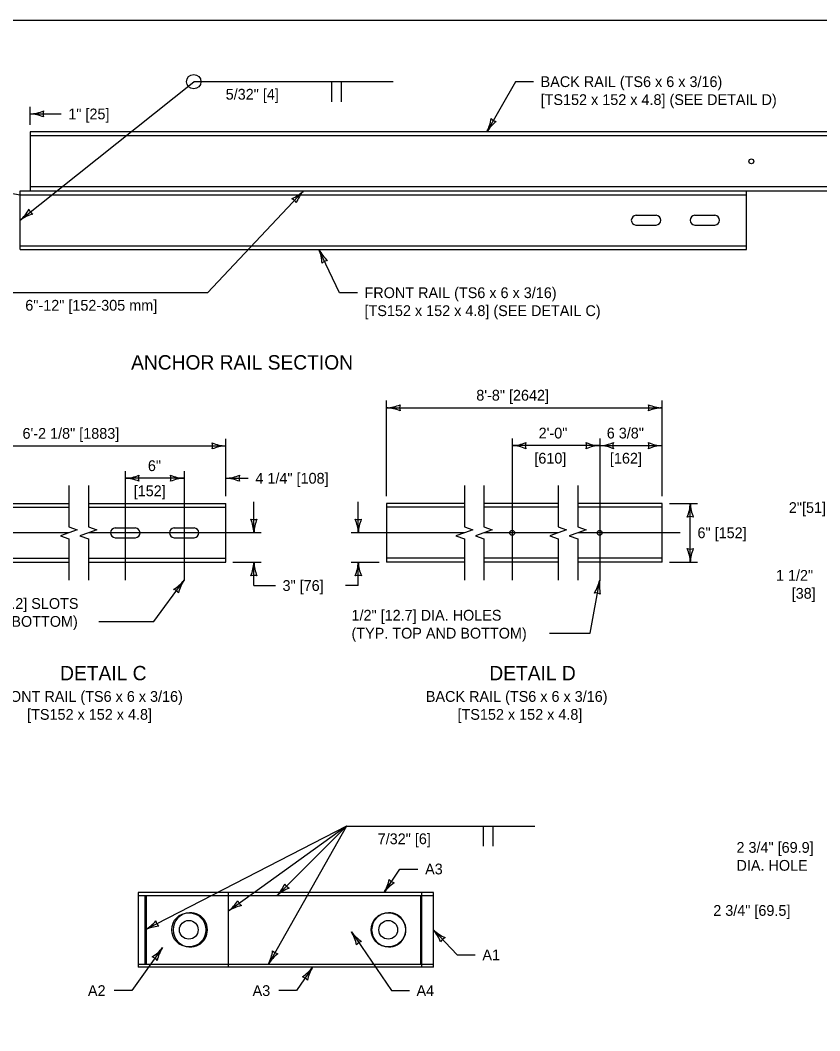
# Model space of a CAD drawing. Extents: x 49991.4 to 50021, y 49987.6 to 50011.4.
# Drawn here: x 50009.75 to 50014.2, y 49993.37 to 49999 of the extents above; entities that cross this region are included whole.
import ezdxf

# ---------------------------------------------------------------- set-up
doc = ezdxf.new("R2010")
doc.units = 0
for name, color, linetype in [('Level 1', 7, 'Continuous'), ('Level 2', 7, 'Continuous'), ('Level 3', 7, 'Continuous'), ('Level 4', 7, 'Continuous'), ('Level 5', 7, 'Continuous'), ('Level 6', 7, 'Continuous')]:
    doc.layers.add(name, color=color, linetype=linetype)

msp = doc.modelspace()

# ---------------------------------------------------------------- linework, layer by layer
at = {"layer": 'Level 1'}
for p, q in [((50015.4779, 49998.377), (50009.801, 49998.377)), ((50009.801, 49998.377), (50009.801, 49998.0488)), ((50009.7464, 49998.0488), (50015.4779, 49998.0488)), ((50009.7464, 49997.7213), (50009.7464, 49998.0488)), ((50013.7926, 49997.7213), (50013.7926, 49998.0488)), ((50013.1773, 49997.9123), (50013.289, 49997.9123)), ((50013.5048, 49997.9123), (50013.6165, 49997.9123)), ((50013.177, 49997.8578), (50013.2892, 49997.8578)), ((50013.5045, 49997.8578), (50013.6167, 49997.8578)), ((50009.7464, 49997.7213), (50013.7926, 49997.7213)), ((50009.3555, 49996.3075), (50010.0174, 49996.3075)), ((50010.126, 49996.3075), (50010.8916, 49996.3075)), ((50010.8916, 49995.98), (50010.8916, 49996.3075)), ((50011.7869, 49996.3075), (50011.7869, 49995.98)), ((50012.2209, 49996.3075), (50011.7869, 49996.3075)), ((50012.7438, 49996.3075), (50012.3295, 49996.3075)), ((50013.323, 49996.3075), (50012.8524, 49996.3075)), ((50013.323, 49995.98), (50013.323, 49996.3075)), ((50010.2762, 49996.1709), (50010.3879, 49996.1709)), ((50010.6037, 49996.1709), (50010.7154, 49996.1709)), ((50010.276, 49996.1163), (50010.3882, 49996.1163)), ((50010.6035, 49996.1163), (50010.7157, 49996.1163)), ((50009.3555, 49995.98), (50010.0174, 49995.98)), ((50010.126, 49995.98), (50010.8916, 49995.98)), ((50012.2209, 49995.98), (50011.7869, 49995.98)), ((50012.7438, 49995.98), (50012.3295, 49995.98)), ((50013.323, 49995.98), (50012.8524, 49995.98)), ((50012.0487, 49994.1404), (50010.4037, 49994.1404)), ((50010.4037, 49994.1404), (50010.4037, 49993.7237)), ((50010.4037, 49994.1231), (50012.0487, 49994.1231)), ((50010.4428, 49993.7411), (50010.4428, 49994.1231)), ((50010.9069, 49993.7237), (50010.9069, 49994.1404)), ((50011.9792, 49993.7411), (50011.9792, 49994.1231)), ((50011.9844, 49993.7237), (50011.9844, 49994.1404)), ((50012.0487, 49993.7237), (50012.0487, 49994.1404)), ((50010.4037, 49993.7411), (50012.0487, 49993.7411)), ((50012.0487, 49993.7237), (50010.4037, 49993.7237))]:
    msp.add_line(p, q, dxfattribs=at)
msp.add_lwpolyline([(49999.3835, 49998.9992), (50016.7501, 49998.9992), (50016.7501, 49987.7988), (49999.3835, 49987.7988)], close=True, dxfattribs=at)
for centre, radius in [((50013.8199, 49998.2132), 0.0136), ((50012.487, 49996.1437), 0.0136), ((50012.975, 49996.1437), 0.0136), ((50010.6858, 49993.9321), 0.0955), ((50011.7969, 49993.9321), 0.0955), ((50010.6858, 49993.9321), 0.0521), ((50011.7969, 49993.9321), 0.0521)]:
    msp.add_circle(centre, radius, dxfattribs=at)
for centre, radius, start, end in [((50013.1785, 49997.885), 0.0273, 92.5686, 266.9422), ((50013.2878, 49997.885), 0.0273, 273.0578, 87.4314), ((50013.506, 49997.885), 0.0273, 92.5686, 266.9422), ((50013.6153, 49997.885), 0.0273, 273.0578, 87.4314), ((50010.2774, 49996.1436), 0.0273, 92.5686, 266.9422), ((50010.3867, 49996.1436), 0.0273, 273.0578, 87.4314), ((50010.6049, 49996.1436), 0.0273, 92.5686, 266.9422), ((50010.7142, 49996.1436), 0.0273, 273.0578, 87.4314), ((50010.6941, 49993.9321), 0.0955, 92.4902, 267.5098), ((50011.8, 49993.9321), 0.0955, 90.9215, 269.0785)]:
    msp.add_arc(centre, radius, start, end, dxfattribs=at)
at = {"layer": 'Level 3'}
for p, q in [((50009.7464, 49997.8851), (50010.7131, 49998.6568)), ((50011.8238, 49998.6568), (50010.7131, 49998.6568)), ((50011.4804, 49998.6568), (50011.4804, 49998.5453)), ((50011.5339, 49998.6568), (50011.5339, 49998.5453)), ((50009.801, 49998.417), (50009.801, 49998.517)), ((50009.801, 49998.477), (50009.9745, 49998.477)), ((50011.7869, 49996.3475), (50011.7869, 49996.8801)), ((50013.323, 49996.3475), (50013.323, 49996.8801)), ((50011.7869, 49996.8401), (50013.323, 49996.8401)), ((50010.8916, 49996.3475), (50010.8916, 49996.6675)), ((50009.3555, 49996.6275), (50010.8916, 49996.6275)), ((50012.975, 49996.6292), (50012.487, 49996.6292)), ((50012.975, 49996.6292), (50013.323, 49996.6292)), ((50010.6596, 49996.4475), (50010.3321, 49996.4475)), ((50010.8916, 49996.4475), (50011.0168, 49996.4475)), ((50011.0484, 49996.1437), (50011.0484, 49996.3171)), ((50011.6301, 49996.1437), (50011.6301, 49996.3171)), ((50013.363, 49996.3075), (50013.5198, 49996.3075)), ((50013.4798, 49995.98), (50013.4798, 49996.3075)), ((50010.9316, 49995.98), (50011.0884, 49995.98)), ((50011.0484, 49995.8499), (50011.0484, 49995.98)), ((50011.5901, 49995.98), (50011.7469, 49995.98)), ((50011.6301, 49995.8499), (50011.6301, 49995.98)), ((50013.363, 49995.98), (50013.5198, 49995.98)), ((50010.491, 49995.65), (50010.6596, 49995.88)), ((50012.9225, 49995.5845), (50012.975, 49995.88)), ((50011.0484, 49995.8499), (50011.1679, 49995.8499)), ((50011.6301, 49995.8499), (50011.559, 49995.8499)), ((50010.1847, 49995.65), (50010.491, 49995.65)), ((50012.6959, 49995.5845), (50012.9225, 49995.5845)), ((50011.5644, 49994.5089), (50010.4428, 49993.9321)), ((50011.5644, 49994.5089), (50010.9069, 49994.0362)), ((50011.5644, 49994.5089), (50011.1298, 49993.7411)), ((50011.5644, 49994.5089), (50011.1786, 49994.1231)), ((50012.3258, 49994.5089), (50012.3258, 49994.3974)), ((50012.3793, 49994.5089), (50012.3793, 49994.3974)), ((50012.0487, 49993.9321), (50012.1814, 49993.7923)), ((50010.5395, 49993.8332), (50010.369, 49993.5934)), ((50012.1814, 49993.7923), (50012.2814, 49993.7923)), ((50010.369, 49993.5934), (50010.269, 49993.5934))]:
    msp.add_line(p, q, dxfattribs=at)
for points in [[(50012.6058, 49998.6568), (50012.5058, 49998.6568), (50012.3465, 49998.377)], [(50011.3246, 49998.0488), (50010.7894, 49997.4811), (50008.2254, 49997.4811)], [(50011.6247, 49997.4811), (50011.5247, 49997.4811), (50011.4108, 49997.7213)], [(50011.5644, 49994.5089), (50012.6133, 49994.5089)], [(50011.7736, 49994.1404), (50011.8623, 49994.2708), (50011.9623, 49994.2708)], [(50011.5916, 49993.9207), (50011.8144, 49993.5934), (50011.9144, 49993.5934)], [(50011.3753, 49993.7237), (50011.2866, 49993.5934), (50011.1866, 49993.5934)]]:
    msp.add_lwpolyline(points, dxfattribs=at)
msp.add_circle((50010.7131, 49998.6568), 0.0401, dxfattribs=at)
msp.add_circle((50010.7131, 49998.6568), 0.0401, dxfattribs=at)
for centre, radius, start, end in [((50009.7919, 49998.6991), 0.2223, 272.3605, 292.544), ((50009.7895, 49998.2443), 0.233, 67.9228, 87.1727), ((50009.9292, 49998.477), 0.0548, 162.1388, 197.8612), ((50012.1386, 49998.4822), 0.233, 333.1604, 352.4103), ((50012.4099, 49998.4884), 0.0548, 222.4719, 258.1943), ((50012.5349, 49998.2591), 0.2223, 127.7891, 147.9726), ((50011.1692, 49998.2078), 0.2223, 294.1475, 314.331), ((50011.2366, 49997.9555), 0.0548, 28.8303, 64.5526), ((50011.5018, 49997.8976), 0.233, 139.5188, 158.7686), ((50009.5923, 49998.0598), 0.233, 311.4286, 330.6784), ((50009.8466, 49997.9651), 0.0548, 200.7401, 236.4624), ((50009.8779, 49997.7057), 0.2223, 106.0573, 126.2408), ((50011.2062, 49997.6344), 0.2223, 2.818, 23.0015), ((50011.6162, 49997.8314), 0.233, 208.1893, 227.4391), ((50011.4657, 49997.6055), 0.0548, 97.5008, 133.2232), ((50011.7754, 49997.0728), 0.233, 272.8273, 292.0772), ((50011.7778, 49996.6179), 0.2223, 67.456, 87.6395), ((50011.9151, 49996.8401), 0.0548, 162.1388, 197.8612), ((50013.3322, 49997.0622), 0.2223, 247.456, 267.6395), ((50013.1948, 49996.8401), 0.0548, 342.1388, 17.8612), ((50013.3345, 49996.6074), 0.233, 92.8273, 112.0772), ((50010.9007, 49996.8496), 0.2223, 247.456, 267.6395), ((50010.7634, 49996.6275), 0.0548, 342.1388, 17.8612), ((50012.4755, 49996.8619), 0.233, 272.8273, 292.0772), ((50012.6152, 49996.6292), 0.0548, 162.1388, 197.8612), ((50012.9842, 49996.8513), 0.2223, 247.456, 267.6395), ((50012.8468, 49996.6292), 0.0548, 342.1388, 17.8612), ((50012.9635, 49996.8619), 0.233, 272.8273, 292.0772), ((50013.1032, 49996.6292), 0.0548, 162.1388, 197.8612), ((50013.3322, 49996.8513), 0.2223, 247.456, 267.6395), ((50013.1948, 49996.6292), 0.0548, 342.1388, 17.8612), ((50010.9031, 49996.3947), 0.233, 92.8273, 112.0772), ((50012.4778, 49996.4071), 0.2223, 67.456, 87.6395), ((50012.9865, 49996.3965), 0.233, 92.8273, 112.0772), ((50012.9659, 49996.4071), 0.2223, 67.456, 87.6395), ((50013.3345, 49996.3965), 0.233, 92.8273, 112.0772), ((50010.3206, 49996.6802), 0.233, 272.8273, 292.0772), ((50010.3229, 49996.2253), 0.2223, 67.456, 87.6395), ((50010.4603, 49996.4475), 0.0548, 162.1388, 197.8612), ((50010.6687, 49996.6696), 0.2223, 247.456, 267.6395), ((50010.5314, 49996.4475), 0.0548, 342.1388, 17.8612), ((50010.6711, 49996.2147), 0.233, 92.8273, 112.0772), ((50010.8824, 49996.6696), 0.2223, 272.3605, 292.544), ((50010.8801, 49996.2147), 0.233, 67.9228, 87.1727), ((50011.0198, 49996.4475), 0.0548, 162.1388, 197.8612), ((50013.2471, 49996.319), 0.233, 337.9228, 357.1727), ((50013.7019, 49996.3166), 0.2223, 182.3605, 202.544), ((50010.8262, 49996.1346), 0.2223, 2.3605, 22.544), ((50011.0484, 49996.2719), 0.0548, 252.1388, 287.8612), ((50011.2811, 49996.1322), 0.233, 157.9228, 177.1727), ((50011.408, 49996.1346), 0.2223, 2.3605, 22.544), ((50011.6301, 49996.2719), 0.0548, 252.1388, 287.8612), ((50011.8628, 49996.1322), 0.233, 157.9228, 177.1727), ((50013.4798, 49996.1792), 0.0548, 72.1388, 107.8612), ((50013.2577, 49995.9708), 0.2223, 2.3605, 22.544), ((50013.4798, 49996.1082), 0.0548, 252.1388, 287.8612), ((50013.7125, 49995.9685), 0.233, 157.9228, 177.1727), ((50010.8157, 49995.9915), 0.233, 337.9228, 357.1727), ((50011.2705, 49995.9891), 0.2223, 182.3605, 202.544), ((50011.3974, 49995.9915), 0.233, 337.9228, 357.1727), ((50011.8523, 49995.9891), 0.2223, 182.3605, 202.544), ((50010.4858, 49996.0186), 0.2223, 301.2263, 321.4098), ((50010.8541, 49995.7517), 0.233, 146.5976, 165.8474), ((50011.0484, 49995.8517), 0.0548, 72.1388, 107.8612), ((50011.6301, 49995.8517), 0.0548, 72.1388, 107.8612), ((50012.7579, 49995.9279), 0.2223, 327.3696, 347.5531), ((50013.2062, 49995.8505), 0.233, 172.7409, 191.9907), ((50010.5838, 49995.7765), 0.0548, 35.9091, 71.6315), ((50012.9526, 49995.7537), 0.0548, 62.0524, 97.7747), ((50011.0059, 49994.2795), 0.233, 317.8273, 337.0772), ((50011.2693, 49994.2137), 0.0548, 207.1388, 242.8612), ((50011.5748, 49994.2619), 0.233, 328.5865, 347.8363), ((50011.9521, 49994.0079), 0.2223, 123.2152, 143.3987), ((50011.8457, 49994.2464), 0.0548, 217.898, 253.6204), ((50011.3292, 49993.9595), 0.2223, 112.456, 132.6395), ((50010.7618, 49994.2185), 0.233, 308.536, 327.7859), ((50011.0291, 49993.8505), 0.2223, 103.1647, 123.3482), ((50011.011, 49994.1111), 0.0548, 197.8475, 233.5699), ((50010.3261, 49994.1338), 0.233, 300.0398, 319.2897), ((50010.5362, 49993.7304), 0.2223, 94.6685, 114.852), ((50010.5568, 49993.9907), 0.0548, 189.3513, 225.0737), ((50011.7701, 49994.0532), 0.2223, 216.6013, 236.7848), ((50011.3927, 49993.7992), 0.233, 12.1637, 31.4135), ((50011.8812, 49993.7858), 0.2223, 20.9666, 41.1501), ((50012.2095, 49994.1006), 0.233, 226.3379, 245.5878), ((50012.1369, 49993.8391), 0.0548, 115.6494, 151.3718), ((50010.3638, 49993.9694), 0.2223, 302.0491, 322.2327), ((50010.7359, 49993.7078), 0.233, 147.4204, 166.6703), ((50011.6637, 49993.8147), 0.0548, 106.3796, 142.102), ((50010.4653, 49993.7287), 0.0548, 36.732, 72.4543), ((50010.9216, 49993.8458), 0.233, 333.3118, 352.5616), ((50011.3186, 49993.6237), 0.2223, 127.9405, 148.124), ((50011.1929, 49993.8527), 0.0548, 222.6233, 258.3457), ((50011.1969, 49993.8563), 0.2223, 303.2152, 323.3987), ((50011.5742, 49993.6023), 0.233, 148.5865, 167.8363), ((50011.3032, 49993.6178), 0.0548, 37.898, 73.6204)]:
    msp.add_arc(centre, radius, start, end, dxfattribs=at)
at = {"layer": 'Level 4'}
for p, q in [((50007.8986, 49998.3395), (50009.7464, 49998.027)), ((50015.4779, 49998.3555), (50009.801, 49998.3555)), ((50015.4779, 49998.071), (50009.801, 49998.071)), ((50009.7464, 49998.027), (50013.7926, 49998.0273)), ((50009.7464, 49997.7431), (50013.7926, 49997.7428)), ((50009.3555, 49996.286), (50010.0174, 49996.286)), ((50010.126, 49996.286), (50010.8916, 49996.286)), ((50012.2209, 49996.286), (50011.7869, 49996.286)), ((50012.7438, 49996.286), (50012.3295, 49996.286)), ((50013.323, 49996.286), (50012.8524, 49996.286)), ((50009.3555, 49996.0015), (50010.0174, 49996.0015)), ((50010.126, 49996.0015), (50010.8916, 49996.0015)), ((50012.2209, 49996.0015), (50011.7869, 49996.0015)), ((50012.7438, 49996.0015), (50012.3295, 49996.0015)), ((50013.323, 49996.0015), (50012.8524, 49996.0015)), ((50010.4501, 49993.7411), (50010.4501, 49994.1231)), ((50010.6858, 49994.0276), (50010.6941, 49994.0276)), ((50010.6858, 49993.8366), (50010.6941, 49993.8366))]:
    msp.add_line(p, q, dxfattribs=at)
for centre, start, end in [((50010.6941, 49993.9321), 267.5098, 92.4902), ((50011.8, 49993.9321), 269.0785, 90.9215)]:
    msp.add_arc(centre, 0.0955, start, end, dxfattribs=at)
at = {"layer": 'Level 5'}
for p, q in [((50012.487, 49996.6692), (50012.487, 49995.88)), ((50012.975, 49996.6692), (50012.975, 49995.88)), ((50010.3321, 49996.4875), (50010.3321, 49995.88)), ((50010.6596, 49996.4875), (50010.6596, 49995.88)), ((50010.0174, 49996.1437), (50009.2555, 49996.1437)), ((50011.0884, 49996.1437), (50010.126, 49996.1437)), ((50012.2209, 49996.1437), (50011.5901, 49996.1437)), ((50012.7438, 49996.1437), (50012.3295, 49996.1437)), ((50013.423, 49996.1437), (50012.8524, 49996.1437))]:
    msp.add_line(p, q, dxfattribs=at)
at = {"layer": 'Level 6'}
for p, q in [((50010.0174, 49996.4074), (50010.0174, 49996.1771)), ((50010.126, 49996.4074), (50010.126, 49996.1771)), ((50012.2209, 49996.4074), (50012.2209, 49996.1771)), ((50012.3295, 49996.4074), (50012.3295, 49996.1771)), ((50012.7438, 49996.4074), (50012.7438, 49996.1771)), ((50012.8524, 49996.4074), (50012.8524, 49996.1771)), ((50010.0174, 49996.1437), (50009.9702, 49996.127)), ((50010.0174, 49996.1771), (50010.0645, 49996.1604)), ((50010.0645, 49996.1604), (50010.0174, 49996.1437)), ((50010.126, 49996.1437), (50010.0788, 49996.127)), ((50010.126, 49996.1771), (50010.1731, 49996.1604)), ((50010.1731, 49996.1604), (50010.126, 49996.1437)), ((50012.2209, 49996.1437), (50012.1738, 49996.127)), ((50012.2209, 49996.1771), (50012.2681, 49996.1604)), ((50012.2681, 49996.1604), (50012.2209, 49996.1437)), ((50012.3295, 49996.1437), (50012.2824, 49996.127)), ((50012.3295, 49996.1771), (50012.3767, 49996.1604)), ((50012.3767, 49996.1604), (50012.3295, 49996.1437)), ((50012.7438, 49996.1437), (50012.6966, 49996.127)), ((50012.7438, 49996.1771), (50012.7909, 49996.1604)), ((50012.7909, 49996.1604), (50012.7438, 49996.1437)), ((50012.8524, 49996.1437), (50012.8052, 49996.127)), ((50012.8524, 49996.1771), (50012.8995, 49996.1604)), ((50012.8995, 49996.1604), (50012.8524, 49996.1437)), ((50009.9702, 49996.127), (50010.0174, 49996.1102)), ((50010.0174, 49996.1102), (50010.0174, 49995.8799)), ((50010.0788, 49996.127), (50010.126, 49996.1102)), ((50010.126, 49996.1102), (50010.126, 49995.8799)), ((50012.1738, 49996.127), (50012.2209, 49996.1102)), ((50012.2209, 49996.1102), (50012.2209, 49995.8799)), ((50012.2824, 49996.127), (50012.3295, 49996.1102)), ((50012.3295, 49996.1102), (50012.3295, 49995.88)), ((50012.6966, 49996.127), (50012.7438, 49996.1102)), ((50012.7438, 49996.1102), (50012.7438, 49995.8799)), ((50012.8052, 49996.127), (50012.8524, 49996.1102)), ((50012.8524, 49996.1102), (50012.8524, 49995.8799))]:
    msp.add_line(p, q, dxfattribs=at)

# ---------------------------------------------------------------- texts
at = {"layer": 'Level 2'}
for s, height, p in [('BACK RAIL (TS6 x 6 x 3/16)', 0.06, (50012.6458, 49998.6268)), ('[TS152 x 152 x 4.8] (SEE DETAIL D)', 0.06, (50012.6458, 49998.5268)), ('1" [25]', 0.06, (50010.0145, 49998.447)), ('FRONT RAIL (TS6 x 6 x 3/16)', 0.06, (50011.6647, 49997.4511)), ('[TS152 x 152 x 4.8] (SEE DETAIL C)', 0.06, (50011.6647, 49997.3511)), ('ANCHOR RAIL SECTION', 0.08, (50010.3643, 49997.0532)), ('8\'-8" [2642]', 0.06, (50012.2874, 49996.8801)), ('6\'-2 1/8" [1883]', 0.06, (50009.7593, 49996.6675)), ('2\'-0"', 0.06, (50012.6349, 49996.6692)), ('6 3/8"', 0.06, (50013.0143, 49996.6692)), ('[610]', 0.06, (50012.6108, 49996.5292)), ('[162]', 0.06, (50013.0319, 49996.5292)), ('6"', 0.06, (50010.4578, 49996.4875)), ('4 1/4" [108]', 0.06, (50011.0568, 49996.4175)), ('[152]', 0.06, (50010.3787, 49996.3475)), ('2"[51]', 0.06, (50014.0287, 49996.2541)), ('1 1/2"', 0.06, (50013.957, 49995.8765)), ('3" [76]', 0.06, (50011.2079, 49995.8199)), ('[38]', 0.06, (50014.0446, 49995.7765)), ('1" x 3" [25.4 x 76.2] SLOTS ', 0.06, (50009.091, 49995.72)), ('1/2" [12.7] DIA. HOLES ', 0.06, (50011.5922, 49995.6545)), ('(TYP. TOP AND BOTTOM)', 0.06, (50009.091, 49995.62)), ('(TYP. TOP AND BOTTOM)', 0.06, (50011.5922, 49995.5545)), ('DETAIL C', 0.08, (50009.9687, 49995.3221)), ('DETAIL D', 0.08, (50012.3601, 49995.3221)), ('FRONT RAIL (TS6 x 6 x 3/16) ', 0.06, (50009.5825, 49995.2021)), ('BACK RAIL (TS6 x 6 x 3/16)', 0.06, (50012.0064, 49995.2021)), ('[TS152 x 152 x 4.8]', 0.06, (50009.785, 49995.1021)), ('[TS152 x 152 x 4.8]', 0.06, (50012.1828, 49995.1021)), ('2 3/4" [69.9]', 0.06, (50013.737, 49994.3611)), ('A3', 0.06, (50012.0023, 49994.2408)), ('DIA. HOLE', 0.06, (50013.737, 49994.2611)), ('2 3/4" [69.5]', 0.06, (50013.6076, 49994.0099)), ('A1', 0.06, (50012.3214, 49993.7623)), ('A2', 0.06, (50010.1237, 49993.5634)), ('A3', 0.06, (50011.0412, 49993.5634)), ('A4', 0.06, (50011.9544, 49993.5634))]:
    msp.add_text(s, height=height, dxfattribs=at).set_placement(p)
for s, p in [(' 5/32" [4]', (50010.869, 49998.5568)), ('6"-12" [152-305 mm]', (50009.7748, 49997.3811)), ('6" [152]', (50013.5198, 49996.1137)), ('7/32" [6]', (50011.7381, 49994.4089))]:
    msp.add_text(s, height=0.06, rotation=360, dxfattribs=at).set_placement(p)

doc.saveas('drawing.dxf')
